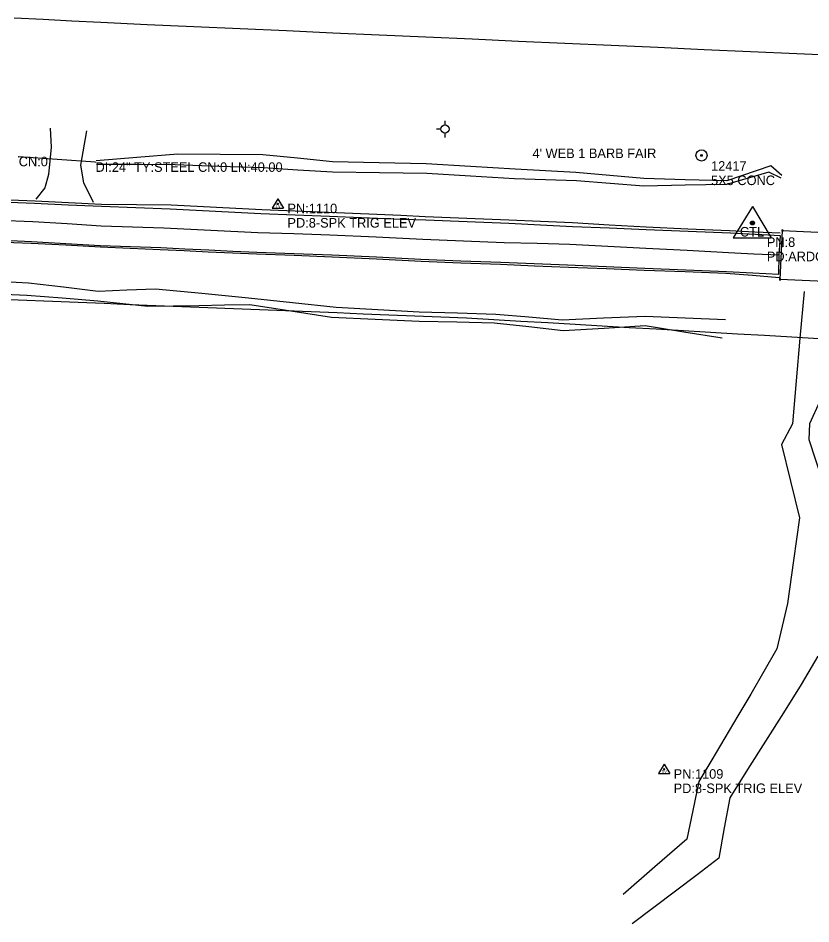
# Model space of a CAD drawing. Extents: x 1138803 to 1169983, y 1655906 to 1658226.
# Drawn here: x 1148823.3 to 1149238.1, y 1657128 to 1657601.6 of the extents above; entities that cross this region are included whole.
import ezdxf

# ---------------------------------------------------------------- set-up
doc = ezdxf.new("R2010")
doc.units = 0
for name, color, linetype in [('S_BRIDGE', 7, 'Continuous'), ('S_DITCHLINE', 7, 'Continuous'), ('S_DRG_PT_SYM', 7, 'Continuous'), ('S_DRIVEWAY', 7, 'Continuous'), ('S_EDGE_PAVEMENT', 7, 'Continuous'), ('S_IRON_PIN', 7, 'Continuous'), ('S_IRON_PIN_ANNOT', 7, 'Continuous'), ('S_MSC_PT_SYM', 7, 'Continuous'), ('S_PAVEMENT_CROWN', 7, 'Continuous'), ('S_PRIMARY_CTL', 7, 'Continuous'), ('S_PRIMARY_CTL_ANNOT', 7, 'Continuous'), ('S_SECONDARY_CTL', 7, 'Continuous'), ('S_SECONDARY_CTL_ANNOT', 7, 'Continuous'), ('S_SHOULDER', 7, 'Continuous'), ('S_SIDE_DRAIN', 7, 'Continuous'), ('S_SIDE_DRAIN_ANNOT', 7, 'Continuous'), ('S_STR_PT_SYM', 7, 'Continuous'), ('S_STREAM', 7, 'Continuous'), ('S_SURVEY_TEXT_ANNOT', 7, 'Continuous'), ('S_TREE', 7, 'Continuous'), ('S_UTILITY_POLE', 7, 'Continuous')]:
    doc.layers.add(name, color=color, linetype=linetype)

msp = doc.modelspace()

# ---------------------------------------------------------------- linework, layer by layer
at = {"layer": 'S_BRIDGE'}
for p, q in [((1149221.93, 1657464.92), (1149223.22, 1657490.51)), ((1149223.22, 1657490.51), (1149300.02, 1657486.84)), ((1149298.91, 1657461.36), (1149221.93, 1657464.92))]:
    msp.add_line(p, q, dxfattribs=at)
at = {"layer": 'S_DITCHLINE'}
for points in [[(1149222.82, 1657519.27), (1149217.1, 1657524.34), (1149194.04, 1657516.48), (1149172.32, 1657517.09), (1149150.61, 1657517.69), (1149132.83, 1657519.28), (1149115.05, 1657520.88), (1149099.18, 1657521.79), (1149083.31, 1657522.7), (1149060.05, 1657524.05), (1149036.78, 1657525.4), (1149012.28, 1657525.97), (1148987.78, 1657526.54), (1148969.54, 1657528.36), (1148951.29, 1657530.19), (1148929.05, 1657530.36), (1148906.81, 1657530.53), (1148885.48, 1657528.8), (1148864.15, 1657527.07)], [(1149222.59, 1657517.95), (1149216.01, 1657521.06), (1149193.95, 1657514.67), (1149172.35, 1657514.21), (1149150.75, 1657513.75), (1149133.11, 1657515.13), (1149115.48, 1657516.52), (1149099.23, 1657517.05), (1149082.97, 1657517.58), (1149060.05, 1657518.94), (1149037.13, 1657520.31), (1149012.44, 1657520.67), (1148987.75, 1657521.03), (1148969.64, 1657522.16), (1148951.53, 1657523.3), (1148928.52, 1657524.08), (1148905.51, 1657524.86), (1148884.92, 1657524.99), (1148864.34, 1657525.13)], [(1149193.32, 1657443.84), (1149172.31, 1657444.69), (1149151.29, 1657445.54), (1149129.59, 1657444.64), (1149107.9, 1657443.73), (1149090.58, 1657445.22), (1149073.26, 1657446.71), (1149053.2, 1657447.3), (1149033.14, 1657447.89), (1149011.46, 1657449.14), (1148989.78, 1657450.39), (1148966.82, 1657452.78), (1148943.86, 1657455.16), (1148919.48, 1657457.55), (1148895.1, 1657459.95), (1148880.18, 1657459.33), (1148865.27, 1657458.71), (1148847.04, 1657460.9), (1148828.82, 1657463.09), (1148809.2, 1657464)], [(1149191.65, 1657434.22), (1149171.52, 1657437.44), (1149151.39, 1657440.67), (1149129.97, 1657439.39), (1149108.56, 1657438.11), (1149090.48, 1657440.13), (1149072.4, 1657442.15), (1149052.76, 1657442.56), (1149033.11, 1657442.98), (1149010.16, 1657444.03), (1148987.21, 1657445.07), (1148965.91, 1657448.41), (1148944.61, 1657451.75), (1148931.26, 1657451.5), (1148917.91, 1657451.25), (1148904.56, 1657451), (1148891.2, 1657450.75), (1148878.1, 1657452.16), (1148865, 1657453.57), (1148846.43, 1657455.11), (1148827.85, 1657456.65), (1148808.21, 1657457.48)]]:
    msp.add_lwpolyline(points, dxfattribs=at)
at = {"layer": 'S_DRG_PT_SYM'}
for points in [[(1148823.64, 1657529.13), (1148823.64, 1657529.18), (1148823.64, 1657529.13), (1148823.59, 1657529.13), (1148823.64, 1657529.13), (1148823.64, 1657529.08), (1148823.64, 1657529.13), (1148823.69, 1657529.13)], [(1148863.8, 1657526.22), (1148863.8, 1657526.27), (1148863.8, 1657526.22), (1148863.75, 1657526.22), (1148863.8, 1657526.22), (1148863.8, 1657526.17), (1148863.8, 1657526.22), (1148863.85, 1657526.22)]]:
    msp.add_lwpolyline(points, dxfattribs=at)
at = {"layer": 'S_DRIVEWAY'}
for points in [[(1148840.06, 1657543.99), (1148840.65, 1657534.12), (1148839.13, 1657519.76), (1148837.27, 1657512.86), (1148832.56, 1657506.96)], [(1148862.82, 1657505.26), (1148857.61, 1657515.42), (1148856.04, 1657524.64), (1148859.31, 1657542.74)]]:
    msp.add_lwpolyline(points, dxfattribs=at)
at = {"layer": 'S_EDGE_PAVEMENT'}
for points in [[(1149221.36, 1657467.49), (1149221.54, 1657477.64), (1149222.14, 1657487.71), (1149209.04, 1657488.4), (1149195.94, 1657489.1), (1149173.96, 1657490.01), (1149151.98, 1657490.92), (1149132.69, 1657491.73), (1149113.39, 1657492.55), (1149096.69, 1657493.43), (1149080, 1657494.3), (1149058.28, 1657495.09), (1149036.56, 1657495.88), (1149023.97, 1657496.36), (1149011.38, 1657496.84), (1148998.8, 1657497.32), (1148986.21, 1657497.8), (1148968.3, 1657498.55), (1148950.38, 1657499.3), (1148926.58, 1657500.48), (1148902.78, 1657501.66), (1148884.89, 1657502.4), (1148866.99, 1657503.14), (1148849.46, 1657503.87), (1148831.93, 1657504.6), (1148814.37, 1657505.33)], [(1149221.36, 1657467.49), (1149207.67, 1657468.26), (1149193.97, 1657469.03), (1149172.62, 1657469.85), (1149151.27, 1657470.68), (1149131, 1657471.6), (1149110.73, 1657472.52), (1149093.33, 1657473.15), (1149075.94, 1657473.77), (1149055.01, 1657474.57), (1149034.09, 1657475.38), (1149010.75, 1657476.54), (1148987.41, 1657477.7), (1148967.8, 1657478.37), (1148948.19, 1657479.04), (1148935.64, 1657479.65), (1148923.08, 1657480.25), (1148910.52, 1657480.86), (1148897.96, 1657481.47), (1148882.14, 1657482.04), (1148866.32, 1657482.6), (1148848.34, 1657483.61), (1148830.37, 1657484.61), (1148811.58, 1657485.5)]]:
    msp.add_lwpolyline(points, dxfattribs=at)
at = {"layer": 'S_IRON_PIN'}
for radius in [2.91, 0.411, 0.262, 0.212, 0.145, 0.0822, 0.0581]:
    msp.add_circle((1149180.86, 1657529.8), radius, dxfattribs=at)
at = {"layer": 'S_MSC_PT_SYM'}
msp.add_lwpolyline([(1149092.41, 1657533.42), (1149092.41, 1657533.47), (1149092.41, 1657533.42), (1149092.36, 1657533.42), (1149092.41, 1657533.42), (1149092.41, 1657533.37), (1149092.41, 1657533.42), (1149092.46, 1657533.42)], dxfattribs=at)
at = {"layer": 'S_PAVEMENT_CROWN'}
msp.add_lwpolyline([(1149221.54, 1657477.64), (1149208.3, 1657478.27), (1149195.06, 1657478.9), (1149173.38, 1657480.05), (1149151.69, 1657481.2), (1149131.8, 1657482.2), (1149111.92, 1657483.19), (1149094.8, 1657483.68), (1149077.68, 1657484.17), (1149056.38, 1657485.01), (1149035.09, 1657485.85), (1149010.72, 1657487), (1148986.36, 1657488.15), (1148967.59, 1657488.76), (1148948.81, 1657489.37), (1148924.14, 1657490.57), (1148899.47, 1657491.76), (1148883.12, 1657492.33), (1148866.77, 1657492.9), (1148848.92, 1657493.97), (1148831.07, 1657495.04), (1148812.84, 1657495.74)], dxfattribs=at)
at = {"layer": 'S_PRIMARY_CTL'}
for p, q in [((1149207.53, 1657503.18), (1149197.5, 1657486.67)), ((1149207.53, 1657503.18), (1149217.36, 1657486.67)), ((1149197.5, 1657486.67), (1149217.36, 1657486.67))]:
    msp.add_line(p, q, dxfattribs=at)
for radius in [1.04, 0.609, 0.344]:
    msp.add_circle((1149207.53, 1657494.48), radius, dxfattribs=at)
at = {"layer": 'S_SECONDARY_CTL'}
for p, q in [((1148959.22, 1657507.19), (1148956.21, 1657502.23)), ((1148959.22, 1657507.19), (1148962.17, 1657502.23)), ((1148956.21, 1657502.23), (1148962.17, 1657502.23)), ((1149161.28, 1657211.54), (1149158.27, 1657206.59)), ((1149161.28, 1657211.54), (1149164.23, 1657206.59)), ((1149158.27, 1657206.59), (1149164.23, 1657206.59))]:
    msp.add_line(p, q, dxfattribs=at)
for centre, radius in [((1148959.22, 1657504.58), 0.311), ((1148959.22, 1657504.58), 0.183), ((1148959.22, 1657504.58), 0.103), ((1149161.28, 1657208.93), 0.311), ((1149161.28, 1657208.93), 0.183), ((1149161.28, 1657208.93), 0.103)]:
    msp.add_circle(centre, radius, dxfattribs=at)
at = {"layer": 'S_SHOULDER'}
for points in [[(1149222.07, 1657489.09), (1149208.75, 1657489.71), (1149195.43, 1657490.33), (1149173.63, 1657491.29), (1149151.83, 1657492.26), (1149132.57, 1657493.41), (1149113.32, 1657494.57), (1149096.7, 1657495.29), (1149080.08, 1657496.02), (1149058.15, 1657496.9), (1149036.22, 1657497.78), (1149023.57, 1657498.35), (1149010.92, 1657498.91), (1148998.27, 1657499.47), (1148985.62, 1657500.04), (1148968.19, 1657500.68), (1148950.76, 1657501.32), (1148927.11, 1657502.57), (1148903.46, 1657503.83), (1148885.22, 1657503.95), (1148866.98, 1657504.07), (1148849.59, 1657505.01), (1148832.19, 1657505.94), (1148814.7, 1657506.63)], [(1149221.43, 1657465.79), (1149207.5, 1657466.98), (1149193.57, 1657468.16), (1149172.22, 1657468.94), (1149150.88, 1657469.72), (1149131.09, 1657470.5), (1149111.31, 1657471.27), (1149093.52, 1657471.99), (1149075.72, 1657472.71), (1149054.92, 1657473.53), (1149034.12, 1657474.34), (1149010.84, 1657475.52), (1148987.55, 1657476.69), (1148967.81, 1657477.45), (1148948.06, 1657478.21), (1148935.44, 1657478.76), (1148922.82, 1657479.31), (1148910.19, 1657479.86), (1148897.57, 1657480.42), (1148881.98, 1657481.17), (1148866.39, 1657481.92), (1148848.22, 1657482.84), (1148830.05, 1657483.76), (1148811.47, 1657484.54)]]:
    msp.add_lwpolyline(points, dxfattribs=at)
at = {"layer": 'S_SIDE_DRAIN'}
msp.add_line((1148863.8, 1657526.22), (1148823.64, 1657529.13), dxfattribs=at)
at = {"layer": 'S_STR_PT_SYM'}
for points in [[(1149223.22, 1657490.51), (1149223.22, 1657491.01), (1149223.22, 1657490.51), (1149222.72, 1657490.51), (1149223.22, 1657490.51), (1149223.22, 1657490.01), (1149223.22, 1657490.51), (1149223.72, 1657490.51)], [(1149221.93, 1657464.92), (1149221.93, 1657465.42), (1149221.93, 1657464.92), (1149221.43, 1657464.92), (1149221.93, 1657464.92), (1149221.93, 1657464.42), (1149221.93, 1657464.92), (1149222.43, 1657464.92)]]:
    msp.add_lwpolyline(points, dxfattribs=at)
at = {"layer": 'S_STREAM'}
for points in [[(1149234.49, 1657458.61), (1149232.27, 1657434.3), (1149230.39, 1657411.89), (1149228.51, 1657389.47), (1149222.63, 1657378.65), (1149227.34, 1657359.53), (1149232.06, 1657340.42), (1149228.96, 1657317.95), (1149225.85, 1657295.48), (1149220.23, 1657271.92), (1149213.43, 1657260.04), (1149206.64, 1657248.16), (1149199.84, 1657236.73), (1149193.03, 1657225.29), (1149186.23, 1657213.86), (1149179.43, 1657202.43), (1149176.31, 1657187.39), (1149173.19, 1657172.35), (1149156.52, 1657157.85), (1149139.84, 1657143.35)], [(1149242.72, 1657401.25), (1149237.39, 1657389.48), (1149236.99, 1657381.35), (1149243.85, 1657360.58)], [(1149241.66, 1657268.04), (1149233.04, 1657253.15), (1149223.69, 1657238.37), (1149214.34, 1657223.59), (1149204.99, 1657208.81), (1149195.64, 1657194.03), (1149192.75, 1657178.19), (1149189.86, 1657162.34), (1149178.55, 1657153.76), (1149167.23, 1657145.19), (1149155.92, 1657136.62), (1149144.61, 1657128.04)]]:
    msp.add_lwpolyline(points, dxfattribs=at)
at = {"layer": 'S_TREE'}
for points in [[(1149255.03, 1657581.82), (1149230.75, 1657582.91), (1149206.48, 1657584), (1149182.2, 1657585.09), (1149157.92, 1657586.18), (1149133.65, 1657587.27), (1149109.37, 1657588.36), (1149085.1, 1657589.45), (1149060.82, 1657590.54), (1149036.55, 1657591.63), (1149012.27, 1657592.72), (1148987.99, 1657593.81), (1148963.72, 1657594.9), (1148939.44, 1657595.99), (1148915.17, 1657597.08), (1148890.89, 1657598.17), (1148866.61, 1657599.26), (1148851.48, 1657600.04), (1148836.34, 1657600.82), (1148821.2, 1657601.6)], [(1149242.21, 1657433.94), (1149228.04, 1657434.77), (1149213.87, 1657435.6), (1149199.7, 1657436.43), (1149185.53, 1657437.26), (1149171.36, 1657438.09), (1149157.18, 1657438.92), (1149143.01, 1657439.75), (1149128.84, 1657440.58), (1149114.67, 1657441.41), (1149100.5, 1657442.24), (1149086.33, 1657443.06), (1149072.15, 1657443.89), (1149057.98, 1657444.72), (1149044.44, 1657445.27), (1149030.89, 1657445.81), (1149017.34, 1657446.35), (1149003.79, 1657446.89), (1148990.24, 1657447.44), (1148976.69, 1657447.98), (1148963.15, 1657448.52), (1148949.6, 1657449.06), (1148936.05, 1657449.6), (1148922.5, 1657450.15), (1148908.95, 1657450.69), (1148895.41, 1657451.23), (1148881.86, 1657451.77), (1148868.31, 1657452.31), (1148854.76, 1657452.86), (1148841.21, 1657453.4), (1148823.4, 1657454.15), (1148805.58, 1657454.9)]]:
    msp.add_lwpolyline(points, dxfattribs=at)
at = {"layer": 'S_UTILITY_POLE'}
for p, q in [((1149046.65, 1657545.71), (1149046.65, 1657547.96)), ((1149044.56, 1657543.58), (1149042.23, 1657543.58)), ((1149046.73, 1657539.16), (1149046.73, 1657541.49))]:
    msp.add_line(p, q, dxfattribs=at)
msp.add_circle((1149046.65, 1657543.6), 2.13, dxfattribs=at)

# ---------------------------------------------------------------- texts
at = {"layer": 'S_IRON_PIN_ANNOT'}
for s, p in [('12417', (1149185.86, 1657521.8)), ('5X5 CONC', (1149185.86, 1657514.3))]:
    msp.add_text(s, height=5, dxfattribs=at).set_placement(p)
at = {"layer": 'S_PRIMARY_CTL'}
msp.add_text('CTL', height=5, rotation=360, dxfattribs=at).set_placement((1149200.95, 1657487.41))
at = {"layer": 'S_PRIMARY_CTL_ANNOT'}
for s, p in [('PN:8', (1149215.03, 1657481.98)), ('PD:ARDOT STD. MON. STAMPED PN:8', (1149215.03, 1657474.48))]:
    msp.add_text(s, height=5, dxfattribs=at).set_placement(p)
at = {"layer": 'S_SECONDARY_CTL'}
for p in [(1148958.01, 1657502.57), (1149160.07, 1657206.92)]:
    msp.add_text('TV', height=1.5, rotation=360, dxfattribs=at).set_placement(p)
at = {"layer": 'S_SECONDARY_CTL_ANNOT'}
for s, p in [('PN:1110', (1148964.22, 1657499.58)), ('PD:8-SPK TRIG ELEV', (1148964.22, 1657492.08)), ('PN:1109', (1149166.28, 1657203.93)), ('PD:8-SPK TRIG ELEV', (1149166.28, 1657196.43))]:
    msp.add_text(s, height=5, dxfattribs=at).set_placement(p)
at = {"layer": 'S_SIDE_DRAIN_ANNOT'}
for s, p in [('CN:0', (1148823.64, 1657524.13)), ('DI:24" TY:STEEL CN:0 LN:40.00', (1148863.8, 1657521.22))]:
    msp.add_text(s, height=5, dxfattribs=at).set_placement(p)
at = {"layer": 'S_SURVEY_TEXT_ANNOT'}
msp.add_text("4' WEB 1 BARB FAIR", height=5, dxfattribs=at).set_placement((1149092.41, 1657528.42))

doc.saveas('drawing.dxf')
